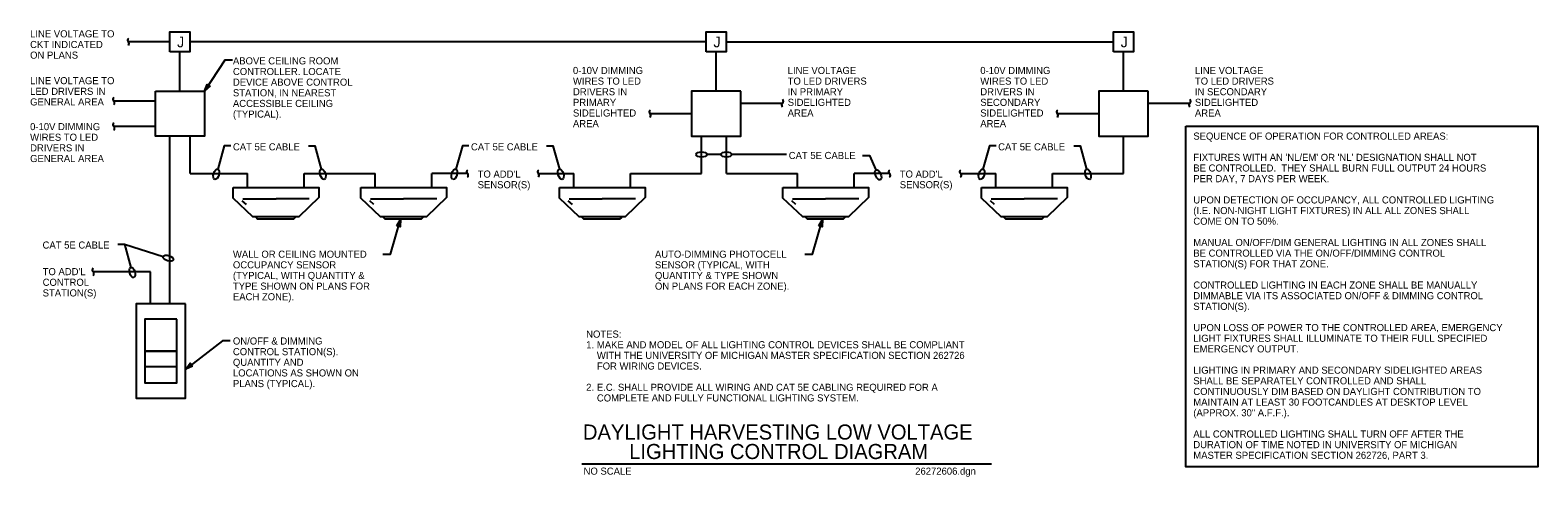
# Model space of a CAD drawing. Extents: x 10113 to 10255, y 10051 to 10093.
import ezdxf

# ---------------------------------------------------------------- set-up
doc = ezdxf.new("R2010")
doc.units = 0
for name, color, linetype in [('G-ANNO-CELL', 7, 'Continuous'), ('G-ANNO-TEXT', 7, 'Continuous'), ('G-DETL-LINE', 7, 'Continuous'), ('Level 3', 7, 'Continuous')]:
    doc.layers.add(name, color=color, linetype=linetype)

msp = doc.modelspace()

# ---------------------------------------------------------------- linework, layer by layer
at = {"layer": 'G-ANNO-CELL'}
msp.add_line((10164.75, 10052.52), (10203.28, 10052.52), dxfattribs=at)
at = {"layer": 'G-ANNO-TEXT'}
for p, q in [((10177.86, 10081.58), (10176.52, 10081.58)), ((10184.02, 10081.58), (10178.86, 10081.58)), ((10121.75, 10073.16), (10125.4, 10071.98))]:
    msp.add_line(p, q, dxfattribs=at)
for points in [[(10131.92, 10090.44), (10131.2, 10090.44), (10129.3, 10087.53)], [(10131.75, 10082.39), (10131.15, 10082.39), (10130.53, 10080.2)], [(10139.05, 10082.39), (10139.65, 10082.39), (10140.27, 10080.2)], [(10154.13, 10082.39), (10153.53, 10082.39), (10152.91, 10080.2)], [(10161.43, 10082.39), (10162.04, 10082.39), (10162.66, 10080.2)], [(10203.71, 10082.39), (10203.1, 10082.39), (10202.48, 10080.2)], [(10211.01, 10082.39), (10211.61, 10082.39), (10212.23, 10080.2)], [(10191.16, 10081.5), (10191.8, 10081.5), (10192.42, 10080.13)], [(10146.05, 10072.23), (10146.76, 10072.23), (10147.71, 10075.48)], [(10185.73, 10072.23), (10186.44, 10072.23), (10187.39, 10075.48)], [(10121.14, 10073.16), (10121.75, 10073.16), (10122.36, 10070.97)], [(10131.7, 10064.08), (10130.97, 10064.08), (10127.53, 10061.42)]]:
    msp.add_lwpolyline(points, dxfattribs=at)
for points in [[(10129.81, 10087.99), (10129.3, 10087.53), (10129.54, 10088.17)], [(10221.57, 10084.26), (10254.65, 10084.26), (10254.65, 10052.24), (10221.57, 10052.24)], [(10147.36, 10074.89), (10147.71, 10075.48), (10147.68, 10074.79)], [(10187.05, 10074.89), (10187.39, 10075.48), (10187.37, 10074.79)], [(10128.16, 10061.7), (10127.53, 10061.42), (10127.95, 10061.96)]]:
    msp.add_lwpolyline(points, close=True, dxfattribs=at)
for centre, major_axis in [((10176.02, 10081.58), (-0.5, 0)), ((10178.36, 10081.58), (-0.5, 0)), ((10130.39, 10079.72), (-0.136, -0.481)), ((10140.41, 10079.72), (0.136, -0.481)), ((10152.78, 10079.72), (-0.136, -0.481)), ((10162.79, 10079.72), (0.136, -0.481)), ((10192.63, 10079.67), (0.206, -0.455)), ((10202.35, 10079.72), (-0.136, -0.481)), ((10212.36, 10079.72), (0.136, -0.481)), ((10125.88, 10071.83), (0.476, -0.153)), ((10122.5, 10070.49), (0.136, -0.481))]:
    msp.add_ellipse(centre, major_axis=major_axis, ratio=0.5, dxfattribs=at)
at = {"layer": 'G-DETL-LINE'}
for p, q in [((10126.04, 10092.16), (10122.13, 10092.16)), ((10176.47, 10092.16), (10127.92, 10092.16)), ((10178.35, 10092.16), (10214.76, 10092.16)), ((10126.98, 10087.53), (10126.98, 10091.22)), ((10177.41, 10087.53), (10177.41, 10091.22)), ((10215.7, 10087.53), (10215.7, 10091.22)), ((10124.67, 10086.61), (10120.75, 10086.61)), ((10179.73, 10086.41), (10183.64, 10086.41)), ((10218.02, 10086.41), (10221.93, 10086.41)), ((10175.09, 10085.41), (10171.18, 10085.41)), ((10213.39, 10085.41), (10209.47, 10085.41)), ((10124.67, 10084.21), (10120.75, 10084.21)), ((10126.03, 10067.55), (10126.03, 10083.29)), ((10127.93, 10079.79), (10127.93, 10083.29)), ((10176.02, 10079.79), (10176.02, 10083.29)), ((10178.36, 10079.79), (10178.36, 10083.29)), ((10215.7, 10079.79), (10215.7, 10083.29)), ((10127.93, 10079.79), (10133.34, 10079.79)), ((10133.34, 10078.47), (10133.34, 10079.79)), ((10138.67, 10078.47), (10138.67, 10079.79)), ((10138.67, 10079.79), (10145.34, 10079.79)), ((10145.34, 10078.47), (10145.34, 10079.79)), ((10150.67, 10078.47), (10150.67, 10079.79)), ((10154.01, 10079.79), (10150.67, 10079.79)), ((10160.68, 10079.79), (10164.02, 10079.79)), ((10164.02, 10078.47), (10164.02, 10079.79)), ((10169.34, 10079.79), (10176.02, 10079.79)), ((10169.34, 10078.47), (10169.34, 10079.79)), ((10178.36, 10079.79), (10185.03, 10079.79)), ((10185.03, 10078.47), (10185.03, 10079.79)), ((10190.36, 10078.47), (10190.36, 10079.79)), ((10193.69, 10079.79), (10190.36, 10079.79)), ((10200.37, 10079.79), (10203.7, 10079.79)), ((10203.7, 10078.47), (10203.7, 10079.79)), ((10209.03, 10079.79), (10215.7, 10079.79)), ((10209.03, 10078.47), (10209.03, 10079.79)), ((10133.22, 10076.88), (10132.82, 10077.24)), ((10132.89, 10077.42), (10136.01, 10077.42)), ((10139.13, 10077.42), (10136.01, 10077.42)), ((10145.22, 10076.88), (10144.82, 10077.24)), ((10144.89, 10077.42), (10148.01, 10077.42)), ((10151.13, 10077.42), (10148.01, 10077.42)), ((10163.89, 10076.88), (10163.49, 10077.24)), ((10163.56, 10077.42), (10166.68, 10077.42)), ((10169.8, 10077.42), (10166.68, 10077.42)), ((10184.9, 10076.88), (10184.5, 10077.24)), ((10184.57, 10077.42), (10187.69, 10077.42)), ((10190.81, 10077.42), (10187.69, 10077.42)), ((10203.57, 10076.88), (10203.18, 10077.24)), ((10203.25, 10077.42), (10206.37, 10077.42)), ((10209.49, 10077.42), (10206.37, 10077.42)), ((10124.22, 10070.55), (10118.8, 10070.55)), ((10124.22, 10067.55), (10124.22, 10070.55)), ((10126.67, 10061.61), (10123.67, 10061.61))]:
    msp.add_line(p, q, dxfattribs=at)
for points in [[(10126.04, 10091.22), (10126.04, 10093.1), (10127.92, 10093.1), (10127.92, 10091.22)], [(10176.47, 10091.22), (10176.47, 10093.1), (10178.35, 10093.1), (10178.35, 10091.22)], [(10214.76, 10091.22), (10214.76, 10093.1), (10216.64, 10093.1), (10216.64, 10091.22)], [(10124.67, 10087.53), (10129.3, 10087.53), (10129.3, 10083.29), (10124.67, 10083.29)], [(10179.73, 10087.53), (10175.09, 10087.53), (10175.09, 10083.29), (10179.73, 10083.29)], [(10218.02, 10087.53), (10213.39, 10087.53), (10213.39, 10083.29), (10218.02, 10083.29)], [(10127.49, 10067.55), (10122.86, 10067.55), (10122.86, 10058.67), (10127.49, 10058.67)], [(10126.67, 10066.11), (10123.67, 10066.11), (10123.67, 10063.11), (10126.67, 10063.11)], [(10126.67, 10063.11), (10123.67, 10063.11), (10123.67, 10060.11), (10126.67, 10060.11)]]:
    msp.add_lwpolyline(points, close=True, dxfattribs=at)
for points in [[(10131.98, 10078.47), (10140.04, 10078.47), (10140.04, 10077.53), (10138.16, 10075.73), (10133.84, 10075.73), (10131.98, 10077.48), (10131.98, 10078.47)], [(10143.98, 10078.47), (10152.04, 10078.47), (10152.04, 10077.53), (10150.16, 10075.73), (10145.84, 10075.73), (10143.98, 10077.48), (10143.98, 10078.47)], [(10162.65, 10078.47), (10170.71, 10078.47), (10170.71, 10077.53), (10168.83, 10075.73), (10164.52, 10075.73), (10162.65, 10077.48), (10162.65, 10078.47)], [(10183.66, 10078.47), (10191.73, 10078.47), (10191.73, 10077.53), (10189.85, 10075.73), (10185.53, 10075.73), (10183.66, 10077.48), (10183.66, 10078.47)], [(10202.33, 10078.47), (10210.4, 10078.47), (10210.4, 10077.53), (10208.52, 10075.73), (10204.2, 10075.73), (10202.33, 10077.48), (10202.33, 10078.47)], [(10137.81, 10075.73), (10137.81, 10075.67), (10137.65, 10075.52), (10134.28, 10075.52), (10134.13, 10075.67), (10134.13, 10075.73)], [(10149.81, 10075.73), (10149.81, 10075.67), (10149.65, 10075.52), (10146.28, 10075.52), (10146.13, 10075.67), (10146.13, 10075.73)], [(10168.48, 10075.73), (10168.48, 10075.67), (10168.32, 10075.52), (10164.95, 10075.52), (10164.8, 10075.67), (10164.8, 10075.73)], [(10189.49, 10075.73), (10189.49, 10075.67), (10189.34, 10075.52), (10185.97, 10075.52), (10185.82, 10075.67), (10185.82, 10075.73)], [(10208.16, 10075.73), (10208.16, 10075.67), (10208.01, 10075.52), (10204.64, 10075.52), (10204.49, 10075.67), (10204.49, 10075.73)]]:
    msp.add_lwpolyline(points, dxfattribs=at)
for centre, start, end in [((10122.25, 10092.33), 126.8699, 233.1301), ((10122, 10092), 306.8699, 53.1301), ((10120.88, 10086.77), 126.8699, 233.1301), ((10120.63, 10086.44), 306.8699, 53.1301), ((10183.76, 10086.24), 126.8699, 233.1301), ((10183.51, 10086.58), 306.8699, 53.1301), ((10222.06, 10086.24), 126.8699, 233.1301), ((10221.81, 10086.58), 306.8699, 53.1301), ((10171.3, 10085.58), 126.8699, 233.1301), ((10171.05, 10085.24), 306.8699, 53.1301), ((10209.6, 10085.58), 126.8699, 233.1301), ((10209.35, 10085.24), 306.8699, 53.1301), ((10120.88, 10084.38), 126.8699, 233.1301), ((10120.63, 10084.04), 306.8699, 53.1301), ((10154.13, 10079.95), 126.8699, 233.1301), ((10153.88, 10079.62), 306.8699, 53.1301), ((10160.8, 10079.95), 126.8699, 233.1301), ((10160.55, 10079.62), 306.8699, 53.1301), ((10193.82, 10079.95), 126.8699, 233.1301), ((10193.57, 10079.62), 306.8699, 53.1301), ((10200.49, 10079.95), 126.8699, 233.1301), ((10200.24, 10079.62), 306.8699, 53.1301), ((10118.93, 10070.72), 126.8699, 233.1301), ((10118.68, 10070.38), 306.8699, 53.1301)]:
    msp.add_arc(centre, 0.208, start, end, dxfattribs=at)

# ---------------------------------------------------------------- texts
at = {"layer": 'G-ANNO-CELL'}
for s, height, p in [('DAYLIGHT HARVESTING LOW VOLTAGE', 1.4167, (10164.87, 10054.79)), ('LIGHTING CONTROL DIAGRAM', 1.4167, (10169.22, 10052.96)), ('NO SCALE', 0.667, (10164.93, 10051.49))]:
    msp.add_text(s, height=height, dxfattribs=at).set_placement(p)
at = {"layer": 'G-ANNO-TEXT'}
for s, height, p in [('CKT INDICATED ', 0.6667, (10112.89, 10091.59)), ('LINE VOLTAGE TO ', 0.6667, (10112.89, 10092.59)), ('ON PLANS', 0.667, (10112.89, 10090.59)), ('ABOVE CEILING ROOM ', 0.6667, (10131.96, 10090.05)), ('CONTROLLER. LOCATE ', 0.6667, (10131.96, 10089.05)), ('0-10V DIMMING ', 0.6667, (10163.93, 10089.15)), ('LINE VOLTAGE ', 0.6667, (10184.12, 10089.15)), ('0-10V DIMMING ', 0.6667, (10202.23, 10089.15)), ('LINE VOLTAGE ', 0.6667, (10222.41, 10089.15)), ('LINE VOLTAGE TO ', 0.6667, (10112.89, 10088.19)), ('LED DRIVERS IN ', 0.6667, (10112.89, 10087.19)), ('STATION, IN NEAREST ', 0.6667, (10131.96, 10087.05)), ('DEVICE ABOVE CONTROL ', 0.6667, (10131.96, 10088.05)), ('WIRES TO LED ', 0.6667, (10163.93, 10088.15)), ('DRIVERS IN ', 0.6667, (10163.93, 10087.15)), ('TO LED DRIVERS ', 0.6667, (10184.12, 10088.15)), ('IN PRIMARY ', 0.6667, (10184.12, 10087.15)), ('WIRES TO LED ', 0.6667, (10202.23, 10088.15)), ('DRIVERS IN ', 0.6667, (10202.23, 10087.15)), ('TO LED DRIVERS ', 0.6667, (10222.41, 10088.15)), ('IN SECONDARY ', 0.6667, (10222.41, 10087.15)), ('GENERAL AREA', 0.6667, (10112.89, 10086.19)), ('ACCESSIBLE CEILING ', 0.6667, (10131.96, 10086.05)), ('PRIMARY ', 0.667, (10163.93, 10086.15)), ('SIDELIGHTED ', 0.6667, (10184.12, 10086.15)), ('SECONDARY ', 0.667, (10202.23, 10086.15)), ('SIDELIGHTED ', 0.6667, (10222.41, 10086.15)), ('(TYPICAL).', 0.667, (10131.96, 10085.05)), ('AREA', 0.667, (10163.93, 10084.15)), ('SIDELIGHTED ', 0.6667, (10163.93, 10085.15)), ('AREA', 0.667, (10184.12, 10085.15)), ('AREA', 0.667, (10202.23, 10084.15)), ('SIDELIGHTED ', 0.6667, (10202.23, 10085.15)), ('AREA', 0.667, (10222.41, 10085.15)), ('WIRES TO LED ', 0.6667, (10112.89, 10082.87)), ('0-10V DIMMING ', 0.6667, (10112.89, 10083.87)), ('SEQUENCE OF OPERATION FOR CONTROLLED AREAS:', 0.6667, (10222.26, 10082.98)), ('DRIVERS IN ', 0.6667, (10112.89, 10081.87)), ('CAT 5E CABLE', 0.6667, (10131.96, 10081.97)), ('CAT 5E CABLE', 0.6667, (10154.34, 10081.97)), ('CAT 5E CABLE', 0.6667, (10203.91, 10081.97)), ('GENERAL AREA', 0.6667, (10112.89, 10080.87)), ('CAT 5E CABLE', 0.6667, (10184.22, 10081.16)), ("FIXTURES WITH AN 'NL/EM' OR 'NL' DESIGNATION SHALL NOT ", 0.6667, (10222.26, 10080.98)), ('BE CONTROLLED.  THEY SHALL BURN FULL OUTPUT 24 HOURS ', 0.6667, (10222.26, 10079.98)), ("TO ADD'L ", 0.667, (10154.97, 10079.41)), ("TO ADD'L ", 0.667, (10194.66, 10079.41)), ('PER DAY, 7 DAYS PER WEEK.', 0.6667, (10222.26, 10078.98)), ('SENSOR(S)', 0.667, (10154.97, 10078.41)), ('SENSOR(S)', 0.667, (10194.66, 10078.41)), ('(I.E. NON-NIGHT LIGHT FIXTURES) IN ALL ALL ZONES SHALL ', 0.6667, (10222.26, 10075.98)), ('UPON DETECTION OF OCCUPANCY, ALL CONTROLLED LIGHTING ', 0.6667, (10222.26, 10076.98)), ('COME ON TO 50%.', 0.6667, (10222.26, 10074.98)), ('MANUAL ON/OFF/DIM GENERAL LIGHTING IN ALL ZONES SHALL ', 0.6667, (10222.26, 10072.98)), ('CAT 5E CABLE', 0.6667, (10114.06, 10072.74)), ('WALL OR CEILING MOUNTED ', 0.6667, (10131.96, 10071.88)), ('AUTO-DIMMING PHOTOCELL ', 0.6667, (10171.64, 10071.88)), ('BE CONTROLLED VIA THE ON/OFF/DIMMING CONTROL ', 0.6667, (10222.26, 10071.98)), ("TO ADD'L ", 0.667, (10114.07, 10070.24)), ('OCCUPANCY SENSOR ', 0.6667, (10131.96, 10070.88)), ('SENSOR (TYPICAL, WITH ', 0.6667, (10171.64, 10070.88)), ('STATION(S) FOR THAT ZONE.', 0.6667, (10222.26, 10070.98)), ('CONTROL ', 0.667, (10114.07, 10069.24)), ('TYPE SHOWN ON PLANS FOR ', 0.6667, (10131.96, 10068.88)), ('(TYPICAL, WITH QUANTITY & ', 0.6667, (10131.96, 10069.88)), ('QUANTITY & TYPE SHOWN ', 0.6667, (10171.64, 10069.88)), ('ON PLANS FOR EACH ZONE).', 0.6667, (10171.64, 10068.88)), ('CONTROLLED LIGHTING IN EACH ZONE SHALL BE MANUALLY ', 0.6667, (10222.26, 10068.98)), ('STATION(S)', 0.667, (10114.07, 10068.24)), ('EACH ZONE).', 0.6667, (10131.96, 10067.88)), ('DIMMABLE VIA ITS ASSOCIATED ON/OFF & DIMMING CONTROL ', 0.6667, (10222.26, 10067.98)), ('STATION(S).', 0.6667, (10222.26, 10066.98)), ('NOTES:', 0.667, (10165.17, 10064.37)), ('UPON LOSS OF POWER TO THE CONTROLLED AREA, EMERGENCY ', 0.6667, (10222.26, 10064.98)), ('ON/OFF & DIMMING ', 0.6667, (10131.96, 10063.72)), ('1.', 0.667, (10165.17, 10063.37)), ('MAKE AND MODEL OF ALL LIGHTING CONTROL DEVICES SHALL BE COMPLIANT ', 0.6667, (10166.18, 10063.37)), ('LIGHT FIXTURES SHALL ILLUMINATE TO THEIR FULL SPECIFIED ', 0.6667, (10222.26, 10063.98)), ('EMERGENCY OUTPUT.', 0.6667, (10222.26, 10062.98)), ('CONTROL STATION(S). ', 0.6667, (10131.96, 10062.72)), ('QUANTITY AND ', 0.6667, (10131.96, 10061.72)), ('WITH THE UNIVERSITY OF MICHIGAN MASTER SPECIFICATION SECTION 262726 ', 0.6667, (10166.18, 10062.37)), ('LOCATIONS AS SHOWN ON ', 0.6667, (10131.96, 10060.72)), ('FOR WIRING DEVICES.', 0.6667, (10166.18, 10061.37)), ('LIGHTING IN PRIMARY AND SECONDARY SIDELIGHTED AREAS ', 0.6667, (10222.26, 10060.98)), ('PLANS (TYPICAL).', 0.6667, (10131.96, 10059.72)), ('2.', 0.667, (10165.17, 10059.37)), ('E.C. SHALL PROVIDE ALL WIRING AND CAT 5E CABLING REQUIRED FOR A ', 0.6667, (10166.18, 10059.37)), ('SHALL BE SEPARATELY CONTROLLED AND SHALL ', 0.6667, (10222.26, 10059.98)), ('CONTINUOUSLY DIM BASED ON DAYLIGHT CONTRIBUTION TO ', 0.6667, (10222.26, 10058.98)), ('COMPLETE AND FULLY FUNCTIONAL LIGHTING SYSTEM.', 0.6667, (10166.18, 10058.37)), ('MAINTAIN AT LEAST 30 FOOTCANDLES AT DESKTOP LEVEL ', 0.6667, (10222.26, 10057.98)), ('(APPROX. 30" A.F.F.).', 0.6667, (10222.26, 10056.98)), ('ALL CONTROLLED LIGHTING SHALL TURN OFF AFTER THE ', 0.6667, (10222.26, 10054.98)), ('DURATION OF TIME NOTED IN UNIVERSITY OF MICHIGAN ', 0.6667, (10222.26, 10053.98)), ('MASTER SPECIFICATION SECTION 262726, PART 3.', 0.6667, (10222.26, 10052.98))]:
    msp.add_text(s, height=height, dxfattribs=at).set_placement(p)
at = {"layer": 'G-DETL-LINE'}
for p in [(10126.71, 10091.66), (10177.14, 10091.66), (10215.43, 10091.66)]:
    msp.add_text('J', height=1, dxfattribs=at).set_placement(p)
at = {"layer": 'Level 3'}
msp.add_text('26272606.dgn', height=0.6667, dxfattribs=at).set_placement((10196.11, 10051.49))

doc.saveas('drawing.dxf')
